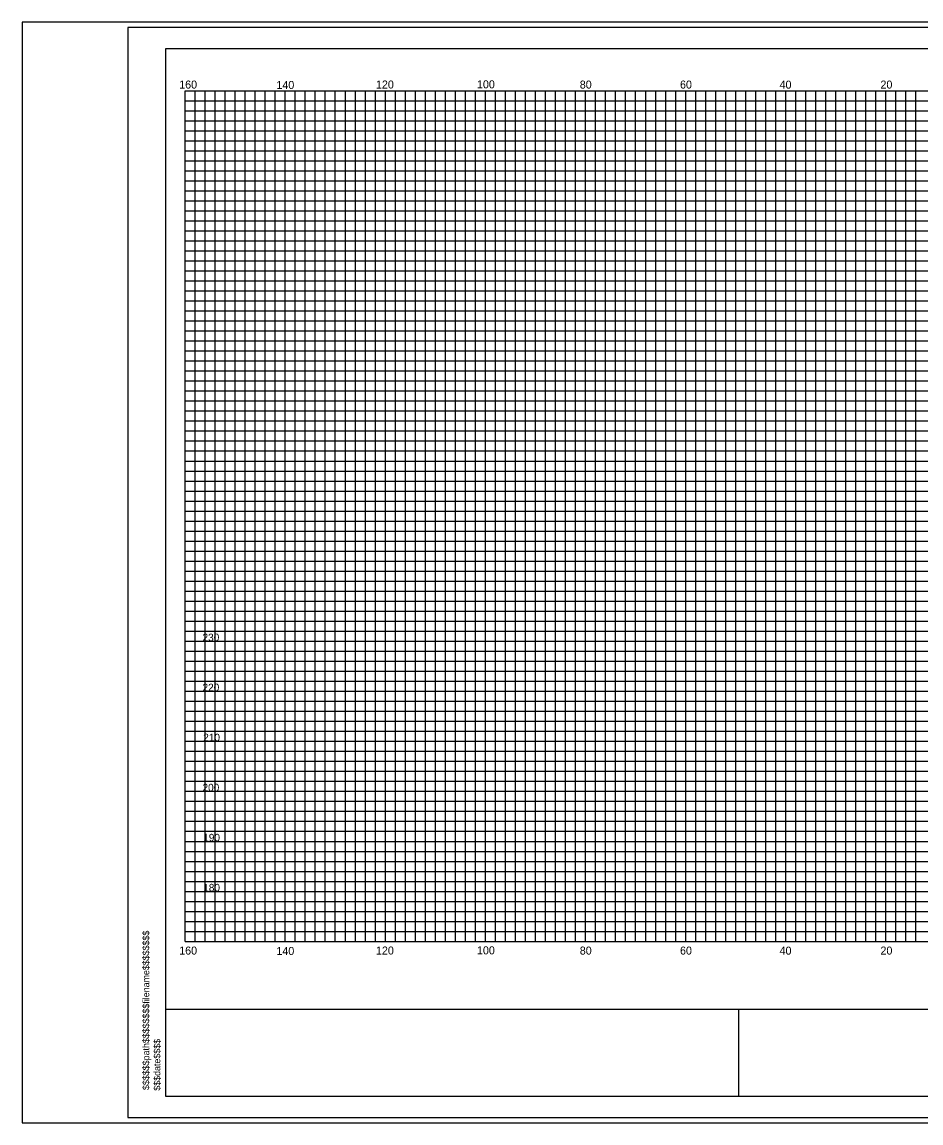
# Model space of a CAD drawing. Extents: x 967 to 1326, y 964 to 2584.
# Drawn here: x 967.4 to 1147, y 2363.7 to 2583.7 of the extents above; entities that cross this region are included whole.
import ezdxf

# ---------------------------------------------------------------- set-up
doc = ezdxf.new("R2010")
doc.units = 0
for name, color, linetype in [('Default', 7, 'Continuous'), ('RD_SHT_Bndy', 7, 'Continuous'), ('RD_SHT_IplotShp', 7, 'Continuous'), ('RD_SHT_MjGrid', 7, 'Continuous'), ('RD_SHT_MnGrid', 7, 'Continuous'), ('RD_SHT_TX', 7, 'Continuous'), ('RD_Sketch1', 7, 'Continuous')]:
    doc.layers.add(name, color=color, linetype=linetype)

msp = doc.modelspace()

# ---------------------------------------------------------------- linework, layer by layer
at = {"layer": 'RD_SHT_Bndy'}
for p, q in [((996.11, 2368.98), (996.11, 2578.46)), ((996.11, 2578.46), (1323.89, 2578.46)), ((996.11, 2386.49), (1323.89, 2386.49)), ((1110.59, 2368.98), (1110.59, 2386.56)), ((1323.89, 2368.98), (996.11, 2368.98))]:
    msp.add_line(p, q, dxfattribs=at)
at = {"layer": 'RD_SHT_IplotShp'}
for points in [[(967.41, 2363.72), (1326.28, 2363.72), (1326.28, 2583.72), (967.41, 2583.72)], [(988.52, 2364.84), (1326.28, 2364.84), (1326.28, 2582.6), (988.52, 2582.6)]]:
    msp.add_lwpolyline(points, close=True, dxfattribs=at)
at = {"layer": 'RD_SHT_MjGrid'}
for p, q in [((1000, 2570), (1320, 2570)), ((1000, 2400), (1000, 2570)), ((1010, 2400), (1010, 2570)), ((1020, 2400), (1020, 2570)), ((1030, 2400), (1030, 2570)), ((1040, 2400), (1040, 2570)), ((1050, 2400), (1050, 2570)), ((1060, 2400), (1060, 2570)), ((1070, 2400), (1070, 2570)), ((1080, 2400), (1080, 2570)), ((1090, 2400), (1090, 2570)), ((1100, 2400), (1100, 2570)), ((1110, 2400), (1110, 2570)), ((1120, 2400), (1120, 2570)), ((1130, 2400), (1130, 2570)), ((1140, 2400), (1140, 2570)), ((1000, 2560), (1320, 2560)), ((1000, 2550), (1320, 2550)), ((1000, 2540), (1320, 2540)), ((1000, 2530), (1320, 2530)), ((1000, 2520), (1320, 2520)), ((1000, 2510), (1320, 2510)), ((1000, 2500), (1320, 2500)), ((1000, 2490), (1320, 2490)), ((1000, 2480), (1320, 2480)), ((1000, 2470), (1320, 2470)), ((1000, 2460), (1320, 2460)), ((1000, 2450), (1320, 2450)), ((1000, 2440), (1320, 2440)), ((1000, 2430), (1320, 2430)), ((1000, 2420), (1320, 2420)), ((1000, 2410), (1320, 2410)), ((1000, 2400), (1320, 2400))]:
    msp.add_line(p, q, dxfattribs=at)
at = {"layer": 'RD_SHT_MnGrid'}
for p, q in [((1002, 2400), (1002, 2570)), ((1004, 2400), (1004, 2570)), ((1006, 2400), (1006, 2570)), ((1008, 2400), (1008, 2570)), ((1012, 2400), (1012, 2570)), ((1014, 2400), (1014, 2570)), ((1016, 2400), (1016, 2570)), ((1018, 2400), (1018, 2570)), ((1022, 2400), (1022, 2570)), ((1024, 2400), (1024, 2570)), ((1026, 2400), (1026, 2570)), ((1028, 2400), (1028, 2570)), ((1032, 2400), (1032, 2570)), ((1034, 2400), (1034, 2570)), ((1036, 2400), (1036, 2570)), ((1038, 2400), (1038, 2570)), ((1042, 2400), (1042, 2570)), ((1044, 2400), (1044, 2570)), ((1046, 2400), (1046, 2570)), ((1048, 2400), (1048, 2570)), ((1052, 2400), (1052, 2570)), ((1054, 2400), (1054, 2570)), ((1056, 2400), (1056, 2570)), ((1058, 2400), (1058, 2570)), ((1062, 2400), (1062, 2570)), ((1064, 2400), (1064, 2570)), ((1066, 2400), (1066, 2570)), ((1068, 2400), (1068, 2570)), ((1072, 2400), (1072, 2570)), ((1074, 2400), (1074, 2570)), ((1076, 2400), (1076, 2570)), ((1078, 2400), (1078, 2570)), ((1082, 2400), (1082, 2570)), ((1084, 2400), (1084, 2570)), ((1086, 2400), (1086, 2570)), ((1088, 2400), (1088, 2570)), ((1092, 2400), (1092, 2570)), ((1094, 2400), (1094, 2570)), ((1096, 2400), (1096, 2570)), ((1098, 2400), (1098, 2570)), ((1102, 2400), (1102, 2570)), ((1104, 2400), (1104, 2570)), ((1106, 2400), (1106, 2570)), ((1108, 2400), (1108, 2570)), ((1112, 2400), (1112, 2570)), ((1114, 2400), (1114, 2570)), ((1116, 2400), (1116, 2570)), ((1118, 2400), (1118, 2570)), ((1122, 2400), (1122, 2570)), ((1124, 2400), (1124, 2570)), ((1126, 2400), (1126, 2570)), ((1128, 2400), (1128, 2570)), ((1132, 2400), (1132, 2570)), ((1134, 2400), (1134, 2570)), ((1136, 2400), (1136, 2570)), ((1138, 2400), (1138, 2570)), ((1142, 2400), (1142, 2570)), ((1144, 2400), (1144, 2570)), ((1146, 2400), (1146, 2570)), ((1000, 2568), (1320, 2568)), ((1000, 2566), (1320, 2566)), ((1000, 2564), (1320, 2564)), ((1000, 2562), (1320, 2562)), ((1000, 2558), (1320, 2558)), ((1000, 2556), (1320, 2556)), ((1000, 2554), (1320, 2554)), ((1000, 2552), (1320, 2552)), ((1000, 2548), (1320, 2548)), ((1000, 2546), (1320, 2546)), ((1000, 2544), (1320, 2544)), ((1000, 2542), (1320, 2542)), ((1000, 2538), (1320, 2538)), ((1000, 2536), (1320, 2536)), ((1000, 2534), (1320, 2534)), ((1000, 2532), (1320, 2532)), ((1000, 2528), (1320, 2528)), ((1000, 2526), (1320, 2526)), ((1000, 2524), (1320, 2524)), ((1000, 2522), (1320, 2522)), ((1000, 2518), (1320, 2518)), ((1000, 2516), (1320, 2516)), ((1000, 2514), (1320, 2514)), ((1000, 2512), (1320, 2512)), ((1000, 2508), (1320, 2508)), ((1000, 2506), (1320, 2506)), ((1000, 2504), (1320, 2504)), ((1000, 2502), (1320, 2502)), ((1000, 2498), (1320, 2498)), ((1000, 2496), (1320, 2496)), ((1000, 2494), (1320, 2494)), ((1000, 2492), (1320, 2492)), ((1000, 2488), (1320, 2488)), ((1000, 2486), (1320, 2486)), ((1000, 2484), (1320, 2484)), ((1000, 2482), (1320, 2482)), ((1000, 2478), (1320, 2478)), ((1000, 2476), (1320, 2476)), ((1000, 2474), (1320, 2474)), ((1000, 2472), (1320, 2472)), ((1000, 2468), (1320, 2468)), ((1000, 2466), (1320, 2466)), ((1000, 2464), (1320, 2464)), ((1000, 2462), (1320, 2462)), ((1000, 2458), (1320, 2458)), ((1000, 2456), (1320, 2456)), ((1000, 2454), (1320, 2454)), ((1000, 2452), (1320, 2452)), ((1000, 2448), (1320, 2448)), ((1000, 2446), (1320, 2446)), ((1000, 2444), (1320, 2444)), ((1000, 2442), (1320, 2442)), ((1000, 2438), (1320, 2438)), ((1000, 2436), (1320, 2436)), ((1000, 2434), (1320, 2434)), ((1000, 2432), (1320, 2432)), ((1000, 2428), (1320, 2428)), ((1000, 2426), (1320, 2426)), ((1000, 2424), (1320, 2424)), ((1000, 2422), (1320, 2422)), ((1000, 2418), (1320, 2418)), ((1000, 2416), (1320, 2416)), ((1000, 2414), (1320, 2414)), ((1000, 2412), (1320, 2412)), ((1000, 2408), (1320, 2408)), ((1000, 2406), (1320, 2406)), ((1000, 2404), (1320, 2404)), ((1000, 2402), (1320, 2402))]:
    msp.add_line(p, q, dxfattribs=at)
at = {"layer": 'RD_Sketch1'}
msp.add_lwpolyline([(967.41, 2363.72), (1326.28, 2363.72), (1326.28, 2583.72), (967.41, 2583.72)], close=True, dxfattribs=at)

# ---------------------------------------------------------------- texts
at = {"layer": 'Default'}
for s, p in [('230', (1003.47, 2460)), ('220', (1003.47, 2450)), ('210', (1003.61, 2440)), ('200', (1003.47, 2430)), ('190', (1003.61, 2420)), ('180', (1003.61, 2410))]:
    msp.add_text(s, height=1.5, dxfattribs=at).set_placement(p)
for s, p in [('$$$$$$path$$$$$$$$filename$$$$$$$$', (992.83, 2370.31)), ('$$$date$$$$', (995.04, 2370.17))]:
    msp.add_text(s, height=1.3258, rotation=90, dxfattribs=at).set_placement(p)
at = {"layer": 'RD_SHT_TX'}
for s, p in [('160', (998.81, 2570.42)), ('140', (1018.23, 2570.34)), ('120', (1038.12, 2570.43)), ('100', (1058.3, 2570.47)), ('80', (1078.84, 2570.42)), ('60', (1098.86, 2570.42)), ('40', (1118.75, 2570.41)), ('20', (1138.91, 2570.42)), ('160', (998.81, 2397.37)), ('140', (1018.23, 2397.29)), ('120', (1038.12, 2397.38)), ('100', (1058.3, 2397.42)), ('80', (1078.84, 2397.37)), ('60', (1098.86, 2397.37)), ('40', (1118.75, 2397.36)), ('20', (1138.91, 2397.37))]:
    msp.add_text(s, height=1.6, dxfattribs=at).set_placement(p)

doc.saveas('drawing.dxf')
